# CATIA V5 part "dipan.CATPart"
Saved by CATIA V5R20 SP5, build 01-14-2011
Part number: dipan
Material "Iron": density 7870 kg/m3, Young's modulus 2.11e+11 Pa, Poisson ratio 0.291, thermal expansion 1.21e-05 1/K
Bounding box of the stored display mesh (mm): x -2790.065 to 3105.028, y -1480 to 1480, z -776.497 to 625
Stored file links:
  C:\Documents and Settings\Student\桌面\zuoping\dipan.CATPart
  C:\Program Files\Dassault Systemes\B20\intel_a\startup\materials\Catalog.CATMaterial
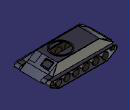
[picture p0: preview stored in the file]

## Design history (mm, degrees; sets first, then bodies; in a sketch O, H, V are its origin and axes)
Body1 (main body), material "Iron"
  Sketch1 on zx-plane, origin (0, 0, 0), H (-1, 0, 0), V (0, 0, 1)
    line L1 (2348.1879, -575) -> (-2315.1727, -575)
    line L2 (-1656.725, 575) -> (1813.6832, 575)
    point P1 (-3008.4503, -221.2709)
    line L3 (-3008.4503, -221.2709) -> (-2315.1727, -575)
    point P2 (-2315.1727, -575)
    line L4 (-3008.4503, -221.2709) -> (-1656.725, 575)
    point P3 (-1656.725, 575)
    point P4 (1813.6832, 575)
    line L5 (1813.6832, 575) -> (2791.5497, 0)
    point P5 (2791.5497, 0)
    line L6 (2791.5497, 0) -> (2348.1879, -575)
    point P6 (2348.1879, -575)
    distance L2 L1 = 1150
    angle L4 L2 = 149.4986
    angle L4 L3 = 57.5333
    angle L2 L5 = 149.5438
    angle L5 L6 = 82.8216
    distance P4 P5 = 1134.3931
    distance P1 P3 = 1568.824
    distance P2 P6 = 4663.3606
    horizontal: L1 H, L2 H
    equidistance: L1 L2 O
  Pad1: profile Sketch1, direction (0, 1, 0), length 900, mirrored extent
  Sketch2 on start face of Pad1, origin (0, -900, 0), H (1, 0, 0), V (0, 0, 1)
    line L1 (-1807.5016, 571.2639) -> (-1807.5016, 111.6163)
    point P1 (-1807.5016, 571.2639)
    point P2 (-1807.5016, 111.6163)
    vertical: L1 V
  Plane1: type 3Points, Element1 Sketch2.P2, Element2 Sketch2.P1, Element3 vertex [face of Pad1 from Sketch1.L2 | end face of Pad1 | face of Pad1 from Sketch1.L5]
  Sketch3 on end face of Pad1, origin (0, 900, 0), H (-1, 0, 0), V (0, 0, 1)
    line L1 (1811.1187, 578.1859) -> (1811.1187, 121.5463)
    point P1 (1811.1187, 578.1859)
    point P2 (1811.1187, 121.5463)
    vertical: L1 V
  Plane2: type 3Points, Element1 Sketch3.P2, Element2 Sketch3.P1, Element3 vertex [face of Pad1 from Sketch1.L2 | start face of Pad1 | face of Pad1 from Sketch1.L5]
  Sketch4 on Plane2, origin (-1812.3973, 2.5822, 0), H (0.0014, 1, 0), V (0, 0, 1)
    line L1 (901.3751, 122.8327) -> (1261.9655, 122.8327)
    line L2 (1261.9655, 122.8327) -> (901.3751, 572.1958)
    horizontal: L1 H
  Sketch5 on Plane1, origin (-1810.5711, -6.2179, 0), H (0.0034, -1, 0), V (0, 0, 1)
    line L1 (889.1693, 109.3655) -> (1282.8057, 109.3655)
    line L2 (1282.8057, 109.3655) -> (889.1693, 570.9105)
    line L3 (889.1693, 570.9105) -> (889.1693, 109.3655)
    horizontal: L1 H
    vertical: L3 V
  Pad2: profile Sketch5, direction (1, 0.0034, 0), length 5000, mirrored extent
  Sketch6 on start face of Pad1, origin (0, -900, 0), H (1, 0, 0), V (0, 0, 1)
    line L1 (1649.6627, 574.4917) -> (3004.6912, -213.5305)
    line L2 (3004.6912, -213.5305) -> (3623.0571, 477.9992)
    line L3 (3623.0571, 477.9992) -> (3133.7415, 1105.2006)
    line L4 (3133.7415, 1105.2006) -> (1649.6627, 574.4917)
    point P5 (-2791.8184, 0)
    line L5 (-2791.8184, 0) -> (-1818.5642, 574.4917)
    line L6 (-1818.5642, 574.4917) -> (-2480.7062, 1423.2206)
    line L7 (-2480.7062, 1423.2206) -> (-7900.3882, 1423.2206)
    line L8 (-7900.3882, 1423.2206) -> (-7378.0488, -446.9143)
    line L9 (-2791.8184, 0) -> (-7378.0488, -446.9143)
    coincidence: P5 H
    parallelism: L6 L3
    horizontal: L7 H
  Pocket1: profile Sketch6, direction (0, -1, 0), length 500, mirrored extent
  Mirror1: of Pad2, about zx-plane
  Mirror2: of Pocket1, about zx-plane
  Sketch7 on face of Pad1 from Sketch1.L2, origin (0, 0, 575), H (1, 0, 0), V (0, 1, 0)
    circle A1 centre (530.7552, 0) radius 700
    point P1 (530.7552, 0)
    circle A2 centre (530.7552, 0) radius 790
    radius A1 = 700
    radius A2 = 790
    coincidence: P1 H
  Pad3: profile Sketch7, direction (0, 0, 1), length 50
  Shell1: ExtOffset 0, Face face of Pad1 from Sketch1.L2, IntOffset 1
  Sketch8 on face of Pad1 from Sketch1.L4, origin (678.2591, 0, 1151.3921), H (0, 1, 0), V (-0.8616, 0, 0.5076)
    line L1 (54.5554, -1277.7391) -> (675.6443, -1277.7391)
    line L2 (675.6443, -1277.7391) -> (675.6443, -1763.0539)
    line L3 (675.6443, -1763.0539) -> (54.5554, -1763.0539)
    line L4 (54.5554, -1763.0539) -> (54.5554, -1277.7391)
    line L5 (29.3761, -1244.2692) -> (709.2167, -1244.2692)
    line L6 (709.2167, -1244.2692) -> (709.2167, -1817.4425)
    line L7 (709.2167, -1817.4425) -> (29.3761, -1817.4425)
    line L8 (29.3761, -1817.4425) -> (29.3761, -1244.2692)
    horizontal: L1 H, L3 H, L5 H, L7 H
    vertical: L2 V, L4 V, L6 V, L8 V
  Pad4: profile Sketch8, direction (0.5076, 0, 0.8616), length 20
  Shell2: ExtOffset 0, Face face of Pad1 from Sketch1.L4, IntOffset 1
  Sketch9 on face of Pad1 from Sketch1.L4, origin (678.2591, 0, 1151.3921), H (0, 1, 0), V (-0.8616, 0, 0.5076)
    line L1 (71.6666, -1312.1312) -> (654.6666, -1312.1312)
    line L2 (654.6666, -1312.1312) -> (654.6666, -1742.1312)
    line L3 (654.6666, -1742.1312) -> (71.6666, -1742.1312)
    line L4 (71.6666, -1742.1312) -> (71.6666, -1312.1312)
    length L2 = 430
    length L3 = 583
    horizontal: L1 H, L3 H
    vertical: L2 V, L4 V
  Pocket2: profile Sketch9, direction (-0.5076, 0, -0.8616), length 20, mirrored extent
  Sketch10 on start face of Pad1, origin (0, -900, 0), H (1, 0, 0), V (0, 0, 1)
    line L1 (2437.988, 107.6764) -> (2820.1838, 107.6764)
    spline S1 through (2838.2119, 107.6764) (3018.4932, 39.3785) (3105.0281, -39.7033)
    line L2 (2437.988, 107.6764) -> (2437.988, 57.2442)
    line L3 (2437.988, 57.2442) -> (2836.894, 57.2442)
    point P4 (2836.894, 57.2442)
    spline S2 through (2836.894, 57.2442) (3003.3044, 16.5474) (3066.1052, -39.7033)
    line L4 (3066.1052, -39.7033) -> (3105.0281, -39.7033)
    point P5 (3066.1052, -39.7033)
    point P6 (3105.0281, -39.7033)
    point P7 (2838.2119, 107.6764)
    point P8 (2836.894, 57.2442)
    point P9 (3066.1052, -39.7033)
    point P10 (3105.0281, -39.7033)
    horizontal: L1 H, L3 H, L4 H
    coincidence: P7 L1, P8 P4, P9 P5, P10 P6
    vertical: L2 V
  Pad5: profile Sketch10, direction (0, -1, 0), length 380
  Mirror3: of Pad5, about zx-plane
  Fillet1: radius 20, on edge [face of Pocket1 from Sketch6.L1 | face of Pad2 from Sketch5.L2]
  Fillet2: radius 20, on edge [face of Mirror1 | face of Mirror2]
  Fillet3: radius 30, on edge [start face of Pad1 | face of Pad1 from Sketch1.L2]
  Fillet4: radius 30, on edge [face of Pad1 from Sketch1.L2 | end face of Pad1]
  Fillet5: radius 40, on edge [face of Mirror2 | face of Mirror1]
  Fillet6: radius 40, on edge [face of Pad2 from Sketch5.L2 | face of Pocket1 from Sketch6.L5]
  Fillet7: radius 20, on edge [face of Pad1 from Sketch1.L5 | face of Pad1 from Sketch1.L6]
  Sketch11 on end face of Pad1, origin (0, 900, 0), H (-1, 0, 0), V (0, 0, 1)
    arc A1 centre (-2678.738, -201.6347) radius 219.6018 from (-2678.738, 17.9671) to (-2763.8849, -404.0574) ccw
    arc A2 centre (-2058.7539, -421.4011) radius 331.9231 from (-2222.1056, -710.3461) to (-2058.7539, -753.3243) ccw
    arc A3 centre (2439.814, -166.1796) radius 246.6706 from (2553.6373, -385.0189) to (2436.8003, 80.4726) ccw
    arc A4 centre (1806.3917, -399.0516) radius 377.4522 from (1804.1275, -776.497) to (2003.1017, -721.1934) ccw
    line L1 (-2678.738, 17.9671) -> (2436.8003, 80.4726)
    line L2 (-2763.8849, -404.0574) -> (-2222.1056, -710.3461)
    line L3 (-2058.7539, -753.3243) -> (1804.1275, -776.497)
    line L4 (2553.6373, -385.0189) -> (2003.1017, -721.1934)
    tangency: L1 A3, L2 A2, L3 A4, L4 A4
  Pad6: profile Sketch11, direction (0, 1, 0), length 580, thin wall 40
  Mirror4: of Pad6, about zx-plane
  Sketch12 on end face of Pad1, origin (0, 900, 0), H (-1, 0, 0), V (0, 0, 1)
    circle A1 centre (-2636.4902, -202.0428) radius 169.394
    circle A2 centre (2404.0977, -166.1507) radius 177.462
    circle A3 centre (-2054.1084, -429.814) radius 264.1797
    circle A4 centre (1814.7078, -429.814) radius 269.6823
    circle A5 centre (-1358.9305, -429.814) radius 267.215
    circle A6 centre (1013.7418, -429.814) radius 288.1128
    circle A7 centre (197.6634, -429.814) radius 285.407
    circle A8 centre (-629.7494, -429.814) radius 283.6867
  Pad7: profile Sketch12, direction (0, 1, 0), length 500
  Mirror5: of Pad7, about zx-plane
  Fillet8: radius 40, on edge [face of Pad7 from Sketch12.A1 | end face of Pad7]; edge [face of Pad7 from Sketch12.A3 | end face of Pad7]; edge [face of Pad7 from Sketch12.A5 | end face of Pad7]; end face of Pad7; edge [face of Pad7 from Sketch12.A7 | end face of Pad7]; edge [face of Pad7 from Sketch12.A6 | end face of Pad7]; edge [face of Pad7 from Sketch12.A4 | end face of Pad7]; edge [face of Pad7 from Sketch12.A2 | end face of Pad7]; edge [face of Mirror5 | face of Mirror5] (x7); face of Mirror5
